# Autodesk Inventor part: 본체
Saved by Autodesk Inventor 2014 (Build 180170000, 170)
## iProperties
Created: 2025-06
Part Number: 본체
Material: 일반
Document SubType Name: Modeling
Designer: dg
Density: 1 g/cm^3
Appearance: 기본값
Author: dg
Author: jhkim
Creation Date: 2025-05-27
Sending System: Autodesk Inventor 2026
Preprocessor: ST-DEVELOPER v20.1
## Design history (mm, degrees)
node "본체1"
node "솔리드1"
node "기준1"
